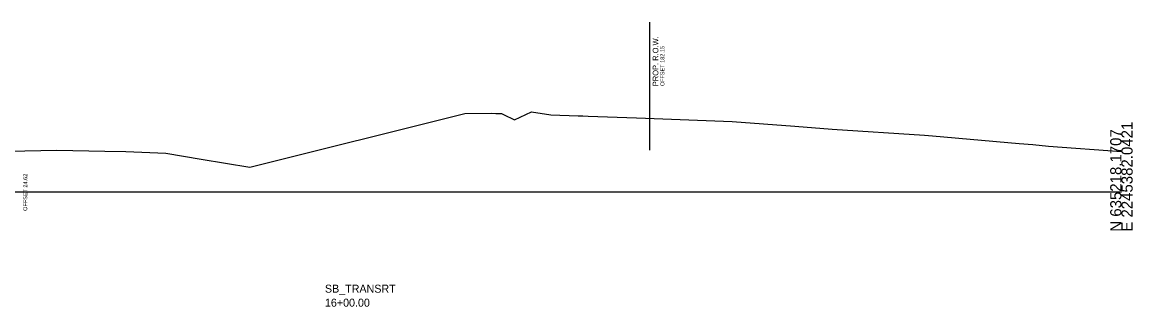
# Model space of a CAD drawing. Extents: x -26 to 669, y -22 to 6560.
# Drawn here: x 325.4 to 602.8, y 5971.2 to 6042.4 of the extents above; entities that cross this region are included whole.
import ezdxf

# ---------------------------------------------------------------- set-up
doc = ezdxf.new("R2010")
doc.units = 0
for name, color, linetype in [('DESIGN - ROW - Right-of-Way and Easement Labels', 7, 'Continuous'), ('DESIGN - ROW - Right-of-Way Linework', 7, 'Continuous'), ('DESIGN - SHEET - Light Grid', 7, 'Continuous'), ('DESIGN - TYPICAL - Subgrade Tie Text', 7, 'Continuous'), ('DESIGN - TYPICAL - Warning Text', 7, 'Continuous'), ('SURVEY - GROUND - Top of Ground', 7, 'Continuous')]:
    doc.layers.add(name, color=color, linetype=linetype)

msp = doc.modelspace()

# ---------------------------------------------------------------- linework, layer by layer
at = {"layer": 'DESIGN - ROW - Right-of-Way Linework'}
msp.add_line((482.15, 6010.37), (482.15, 6042.37), dxfattribs=at)
at = {"layer": 'DESIGN - SHEET - Light Grid'}
msp.add_line((300, 6000), (600, 6000), dxfattribs=at)
at = {"layer": 'SURVEY - GROUND - Top of Ground'}
for p, q in [((382.23, 6006.12), (435.99, 6019.56)), ((322, 6010.12), (334, 6010.36)), ((334, 6010.36), (346, 6010.12)), ((346, 6010.12), (351.23, 6010.02)), ((351.23, 6010.02), (361.23, 6009.62)), ((361.23, 6009.62), (370.09, 6008.14)), ((370.09, 6008.14), (382.23, 6006.12))]:
    msp.add_line(p, q, dxfattribs=at)
msp.add_lwpolyline([(435.99, 6019.56), (442.71, 6019.59), (443.69, 6019.58), (445.13, 6019.57), (445.64, 6019.31), (448.39, 6017.96), (452.58, 6019.97), (457.42, 6019.19), (464.25, 6018.98), (465.43, 6018.93), (466.76, 6018.88), (478.85, 6018.5), (481.11, 6018.37), (502.73, 6017.51), (518.37, 6016.35), (527.77, 6015.66), (550.81, 6014.1), (552.83, 6013.95), (574.46, 6012.04), (577.88, 6011.76), (581.77, 6011.39), (600, 6010.05)], dxfattribs=at)

# ---------------------------------------------------------------- texts
at = {"layer": 'DESIGN - ROW - Right-of-Way and Easement Labels'}
for s, height, p in [('PROP. R.O.W.', 1.4, (484.3, 6026.37)), ('OFFSET 182.15', 1, (485.8, 6026.37))]:
    msp.add_text(s, height=height, rotation=90, dxfattribs=at).set_placement(p)
at = {"layer": 'DESIGN - SHEET - Light Grid'}
for s, p in [('E 2245382.0421', (602.8, 5990)), ('N 635218.1707', (600, 5990))]:
    msp.add_text(s, height=2.8, rotation=90, dxfattribs=at).set_placement(p)
at = {"layer": 'DESIGN - TYPICAL - Subgrade Tie Text'}
msp.add_text('OFFSET 24.62', height=1, rotation=90, dxfattribs=at).set_placement((326.62, 5995.2))
at = {"layer": 'DESIGN - TYPICAL - Warning Text'}
for s, p in [('SB_TRANSRT', (401, 5974.75)), ('SB_TRANSRT', (401, 5974.75)), ('16+00.00', (401, 5971.25)), ('16+00.00', (401, 5971.25))]:
    msp.add_text(s, height=2, dxfattribs=at).set_placement(p)

doc.saveas('drawing.dxf')
